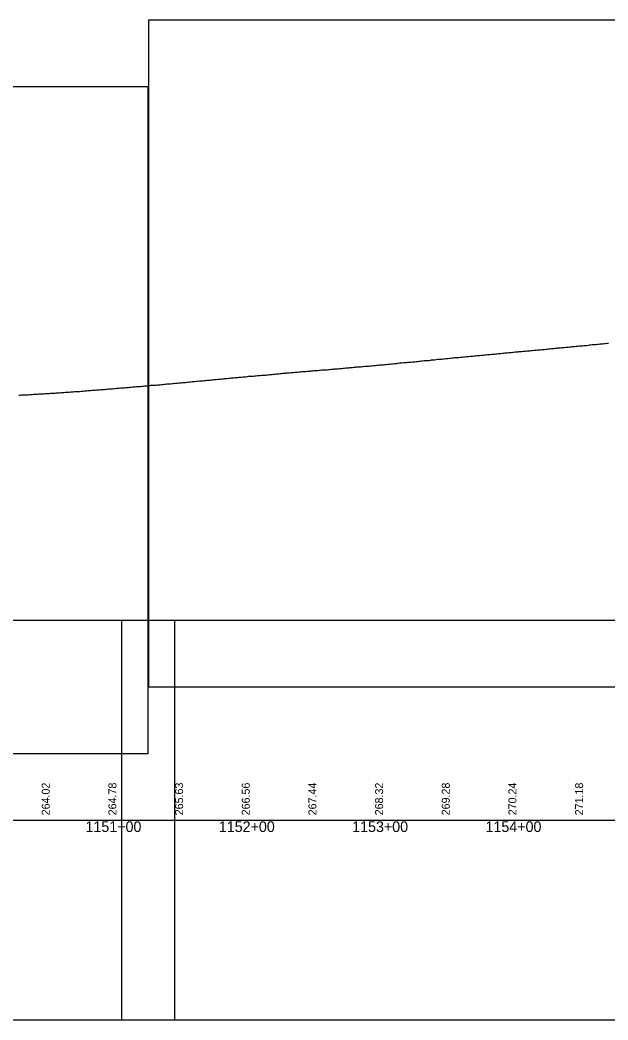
# Model space of a CAD drawing. Extents: x 2898 to 49495, y -15038 to -13538.
# Drawn here: x 4380 to 4821, y -15038 to -14288 of the extents above; entities that cross this region are included whole.
import ezdxf

# ---------------------------------------------------------------- set-up
doc = ezdxf.new("R2010")
doc.units = 0
for name, color, linetype in [('RD_DDB_Profile_EX', 7, 'Continuous'), ('RD_DDB_StaTX', 7, 'Continuous'), ('RD_DDB_StripGrade', 7, 'Continuous'), ('RD_GPK_Profile_Cell', 7, 'Continuous'), ('RD_SHT_ShtClip', 7, 'Continuous')]:
    doc.layers.add(name, color=color, linetype=linetype)

msp = doc.modelspace()

# ---------------------------------------------------------------- linework, layer by layer
at = {"layer": 'RD_DDB_Profile_EX'}
for points in [[(4721.05, -14540.3), (4721.62, -14540.27), (4722.62, -14540.17), (4723.62, -14540.11), (4724.67, -14540.01), (4725.62, -14539.95), (4726.62, -14539.85), (4727.62, -14539.8), (4728.62, -14539.65), (4729.62, -14539.55), (4730.62, -14539.45), (4731.91, -14539.31), (4732.62, -14539.24), (4733.62, -14539.14), (4734.62, -14539.04), (4735.62, -14538.99), (4736.62, -14538.94), (4737.62, -14538.89), (4738.62, -14538.69), (4739.16, -14538.67), (4739.62, -14538.64), (4740.62, -14538.49), (4741.62, -14538.34), (4742.78, -14538.28), (4743.62, -14538.19), (4744.62, -14538.09), (4745.61, -14537.99), (4746.62, -14537.94), (4747.62, -14537.79), (4748.61, -14537.75), (4749.62, -14537.64), (4750.02, -14537.64), (4750.39, -14537.64), (4751.4, -14537.39), (4752.39, -14537.34), (4753.64, -14537.25), (4754.39, -14537.18), (4755.39, -14537.12), (4756.39, -14537.07), (4757.4, -14536.92), (4758.39, -14536.86), (4759.4, -14536.76), (4760.4, -14536.6), (4760.89, -14536.6), (4761.39, -14536.6), (4762.39, -14536.5), (4763.4, -14536.35), (4764.51, -14536.24), (4765.4, -14536.2), (4766.4, -14536.19), (4767.39, -14536.04), (4768.39, -14535.94), (4769.4, -14535.88), (4770.39, -14535.74), (4771.39, -14535.68), (4771.75, -14535.63), (4772.39, -14535.53), (4773.39, -14535.49), (4774.39, -14535.39), (4775.39, -14535.29), (4776.39, -14535.14), (4777.39, -14535.09), (4778.39, -14534.94), (4779, -14534.85), (4779.39, -14534.79), (4780.39, -14534.74), (4781.39, -14534.69), (4782.62, -14534.52), (4783.39, -14534.44), (4784.39, -14534.35), (4785.38, -14534.3), (4786.39, -14534.16), (4787.39, -14534.11), (4788.39, -14533.97), (4789.39, -14533.91), (4790.1, -14533.76), (4791.11, -14533.76), (4792.11, -14533.66), (4793.11, -14533.6), (4793.49, -14533.55), (4794.11, -14533.46), (4795.11, -14533.35), (4796.1, -14533.3), (4797.11, -14533.15), (4798.11, -14533.05), (4799.11, -14532.95), (4800.1, -14532.9), (4800.73, -14532.84), (4801.1, -14532.8), (4802.11, -14532.75), (4803.11, -14532.6), (4804.35, -14532.54), (4805.1, -14532.5), (4806.1, -14532.26), (4807.1, -14532.16), (4808.1, -14532.06), (4809.1, -14531.96), (4810.1, -14531.92), (4811.1, -14531.86), (4811.6, -14531.79), (4812.1, -14531.72)], [(4812.1, -14531.72), (4813.1, -14531.62), (4814.09, -14531.52), (4815.22, -14531.42), (4816.09, -14531.38), (4817.09, -14531.37), (4818.09, -14531.14), (4819.09, -14530.99), (4820.37, -14530.94), (4821.37, -14530.84)], [(4632.3, -14548.69), (4632.77, -14548.66), (4633.76, -14548.61), (4634.12, -14548.59), (4634.77, -14548.56), (4635.76, -14548.5), (4636.76, -14548.45), (4637.77, -14548.3), (4638.77, -14548.15), (4639.76, -14548.04), (4640.77, -14547.99), (4641.36, -14548.02), (4641.76, -14548.04), (4642.77, -14547.84), (4643.76, -14547.73), (4644.99, -14547.67), (4645.77, -14547.63), (4646.77, -14547.48), (4647.76, -14547.38), (4648.76, -14547.23), (4649.77, -14547.18), (4650.77, -14547.13), (4651.76, -14547.03), (4652.23, -14547), (4652.76, -14546.98), (4653.76, -14546.83), (4654.77, -14546.73), (4655.85, -14546.62), (4656.76, -14546.58), (4657.77, -14546.48), (4658.76, -14546.33), (4659.76, -14546.28), (4660.77, -14546.18), (4661.76, -14546.09), (4662.76, -14545.98), (4663.09, -14545.94), (4663.76, -14545.84), (4664.76, -14545.69), (4665.76, -14545.64), (4666.75, -14545.54), (4667.76, -14545.45), (4668.76, -14545.35), (4669.76, -14545.31), (4670.34, -14545.25), (4670.76, -14545.21), (4671.76, -14545.06), (4672.1, -14545.01), (4673.09, -14545), (4674.1, -14544.95), (4675.1, -14544.84), (4676.1, -14544.74), (4677.1, -14544.58), (4677.58, -14544.53), (4678.1, -14544.48), (4679.1, -14544.42), (4680.1, -14544.32), (4681.2, -14544.2), (4682.1, -14544.11), (4683.1, -14543.96), (4684.1, -14543.9), (4685.11, -14543.8), (4686.1, -14543.84), (4687.1, -14543.79), (4688.11, -14543.49), (4688.45, -14543.46), (4689.1, -14543.39), (4690.11, -14543.33), (4691.1, -14543.23), (4692.1, -14543.08), (4693.11, -14542.93), (4694.11, -14542.92), (4695.11, -14542.82), (4695.69, -14542.76), (4696.1, -14542.72), (4697.1, -14542.67), (4698.11, -14542.52), (4699.31, -14542.44), (4700.1, -14542.32), (4701.11, -14542.22), (4702.1, -14542.17), (4703.11, -14542.12), (4704.11, -14541.87), (4705.1, -14541.77), (4706.11, -14541.67), (4706.56, -14541.63), (4707.1, -14541.57), (4708.11, -14541.47), (4709.1, -14541.47), (4710.18, -14541.33), (4710.63, -14541.32), (4711.62, -14541.22), (4712.62, -14541.21), (4713.8, -14541.12), (4714.62, -14540.95), (4715.62, -14540.85), (4716.62, -14540.74), (4717.63, -14540.68), (4718.62, -14540.53), (4719.62, -14540.48), (4720.62, -14540.33), (4721.05, -14540.3)], [(4540.37, -14556.74), (4541.37, -14556.65), (4542.37, -14556.65), (4543.57, -14556.55), (4544.37, -14556.4), (4545.37, -14556.3), (4546.37, -14556.25), (4547.37, -14556.15), (4548.37, -14556.1), (4549.37, -14556), (4550.37, -14555.9), (4550.81, -14555.81), (4551.36, -14555.7), (4552.37, -14555.66), (4553.2, -14555.65), (4554.44, -14555.62), (4555.2, -14555.55), (4556.2, -14555.45), (4557.2, -14555.34), (4558.2, -14555.19), (4559.2, -14555.19), (4560.2, -14555.13), (4561.2, -14554.93), (4561.68, -14554.91), (4562.21, -14554.88), (4563.21, -14554.78), (4564.2, -14554.72), (4565.3, -14554.61), (4566.2, -14554.52), (4567.2, -14554.37), (4568.2, -14554.27), (4569.2, -14554.22), (4570.2, -14554.17), (4571.2, -14554.02), (4572.2, -14553.96), (4572.55, -14553.91), (4573.2, -14553.82), (4574.2, -14553.77), (4575.19, -14553.66), (4576.19, -14553.56), (4577.2, -14553.46), (4578.2, -14553.42), (4579.2, -14553.27), (4579.79, -14553.24), (4580.2, -14553.21), (4581.2, -14553.12), (4582.2, -14553.07), (4583.41, -14552.9), (4584.2, -14552.82), (4585.2, -14552.77), (4586.19, -14552.67), (4587.19, -14552.62), (4588.19, -14552.47), (4589.49, -14552.37), (4590.66, -14552.25), (4591.49, -14552.17), (4592.48, -14552.07), (4593.49, -14552.06), (4594.48, -14552.01), (4595.48, -14551.91), (4596.48, -14551.86), (4597.48, -14551.76), (4597.9, -14551.72), (4598.48, -14551.66), (4599.48, -14551.51), (4600.48, -14551.46), (4601.52, -14551.36), (4602.48, -14551.31), (4603.48, -14551.25), (4604.48, -14551.16), (4605.14, -14551.09), (4605.49, -14551.06), (4606.48, -14550.96), (4607.48, -14550.86), (4608.77, -14550.79), (4609.48, -14550.76), (4610.48, -14550.75), (4611.47, -14550.61), (4612.48, -14550.51), (4613.48, -14550.41), (4614.48, -14550.36), (4615.48, -14550.22), (4616.01, -14550.16), (4616.48, -14550.12), (4617.48, -14550.07), (4618.48, -14549.97), (4619.63, -14549.91), (4620.48, -14549.83), (4621.47, -14549.73), (4622.48, -14549.63), (4623.48, -14549.58), (4624.47, -14549.44), (4625.48, -14549.34), (4626.47, -14549.35), (4626.88, -14549.29), (4627.47, -14549.2), (4628.47, -14549.11), (4629.48, -14549.01), (4630.5, -14548.91), (4631.76, -14548.72), (4632.3, -14548.69)], [(4445.46, -14565.28), (4446.46, -14565.13), (4447.45, -14565.08), (4448.45, -14565.03), (4449.46, -14564.97), (4450.45, -14564.93), (4451.46, -14564.82), (4452.46, -14564.63), (4453.46, -14564.58), (4454.46, -14564.53), (4455.46, -14564.43), (4456.46, -14564.38), (4457.46, -14564.28), (4458.45, -14564.23), (4459.46, -14564.13), (4460.46, -14564.03), (4461.46, -14563.98), (4462.46, -14563.93), (4463.46, -14563.78), (4464.46, -14563.68), (4465.46, -14563.58), (4466.45, -14563.48), (4467.45, -14563.38), (4468.46, -14563.33), (4469.46, -14563.28), (4470.46, -14563.23), (4471.45, -14563.08), (4472.46, -14562.98), (4473.45, -14562.88), (4474.42, -14562.84), (4475.14, -14562.83), (4476.15, -14562.68), (4477.15, -14562.53), (4478.14, -14562.43), (4479.15, -14562.42), (4480.15, -14562.42), (4481.14, -14562.27), (4482.15, -14562.22), (4483.14, -14562.12), (4484.15, -14562.02), (4485.15, -14562.01), (4486.14, -14561.81), (4487.14, -14561.76), (4488.14, -14561.66), (4489.15, -14561.56), (4490.14, -14561.41), (4491.13, -14561.41), (4492.14, -14561.3), (4493.14, -14561.25), (4494.13, -14561.15), (4495.14, -14561), (4496.13, -14560.89), (4496.48, -14560.88), (4497.14, -14560.84), (4498.14, -14560.74), (4499.13, -14560.64), (4500.14, -14560.59), (4501.14, -14560.49), (4502.14, -14560.34), (4503.13, -14560.29), (4503.73, -14560.31), (4504.13, -14560.33), (4505.14, -14560.08), (4506.13, -14559.98), (4507.35, -14559.82), (4508.13, -14559.78), (4509.13, -14559.68), (4510.14, -14559.58), (4511.13, -14559.48), (4512.13, -14559.38), (4513.13, -14559.28), (4514.59, -14559.17), (4515.37, -14559.13), (4516.37, -14559.03), (4517.37, -14558.97), (4518.36, -14558.87), (4519.37, -14558.77), (4520.41, -14558.71), (4521.37, -14558.61), (4521.84, -14558.57), (4522.37, -14558.51), (4523.37, -14558.41), (4524.37, -14558.31), (4525.46, -14558.14), (4526.37, -14558.01), (4527.37, -14558), (4528.37, -14557.95), (4529.37, -14557.85), (4530.37, -14557.8), (4531.37, -14557.65), (4532.37, -14557.5), (4532.7, -14557.48), (4533.37, -14557.45), (4534.37, -14557.35), (4535.37, -14557.25), (4536.37, -14557.15), (4537.36, -14557.09), (4538.37, -14556.95), (4539.37, -14556.84), (4539.95, -14556.79), (4540.37, -14556.74)], [(4379.21, -14569.75), (4380.21, -14569.74), (4381.21, -14569.7), (4382.2, -14569.65), (4383.21, -14569.65), (4384.21, -14569.6), (4385.21, -14569.54), (4386.21, -14569.49), (4387.21, -14569.4), (4388.21, -14569.35), (4389.21, -14569.25), (4390.21, -14569.2), (4391.21, -14569.15), (4392.21, -14569.1), (4393.21, -14569.05), (4394.21, -14568.95), (4394.88, -14568.95), (4395.88, -14568.85), (4396.89, -14568.9), (4397.89, -14568.8), (4398.88, -14568.6), (4399.88, -14568.6), (4400.89, -14568.65), (4401.89, -14568.5), (4402.88, -14568.4), (4403.89, -14568.35), (4404.88, -14568.3), (4405.89, -14568.26), (4406.89, -14568.2), (4407.89, -14568.11), (4408.88, -14568.06), (4409.89, -14568.01), (4410.89, -14567.91), (4411.89, -14567.91), (4412.89, -14567.81), (4413.89, -14567.71), (4414.89, -14567.71), (4415.89, -14567.56), (4416.89, -14567.51), (4417.89, -14567.46), (4418.88, -14567.41), (4419.89, -14567.36), (4420.89, -14567.21), (4421.89, -14567.16), (4422.87, -14567.12), (4423.87, -14567.12), (4424.88, -14567.02), (4425.87, -14566.92), (4426.87, -14566.77), (4427.87, -14566.67), (4428.88, -14566.57), (4429.87, -14566.52), (4430.87, -14566.42), (4431.87, -14566.37), (4432.87, -14566.27), (4433.87, -14566.18), (4434.45, -14566.12), (4435.45, -14566.07), (4436.46, -14565.97), (4437.46, -14565.87), (4438.46, -14565.87), (4439.46, -14565.72), (4440.45, -14565.67), (4441.46, -14565.62), (4442.45, -14565.52), (4443.45, -14565.47), (4444.46, -14565.37), (4445.46, -14565.28)]]:
    msp.add_lwpolyline(points, dxfattribs=at)
at = {"layer": 'RD_GPK_Profile_Cell'}
msp.add_line((2976.05, -14888.47), (48721.13, -14888.47), dxfattribs=at)
at = {"layer": 'RD_SHT_ShtClip'}
for points in [[(5976.22, -14788.47), (5976.22, -14288.47), (5976.22, -14288.47), (4476.38, -14288.47), (4476.38, -14788.47)], [(4476.22, -14838.47), (4476.22, -14338.47), (4476.22, -14338.47), (2976.38, -14338.47), (2976.38, -14838.47)], [(2956.38, -14738.47), (4496.05, -14738.47), (4496.05, -15038.47), (2956.38, -15038.47)], [(4456.38, -14738.47), (5996.05, -14738.47), (5996.05, -15038.47), (4456.38, -15038.47)]]:
    msp.add_lwpolyline(points, close=True, dxfattribs=at)

# ---------------------------------------------------------------- texts
at = {"layer": 'RD_DDB_StaTX'}
for s, p in [('1151+00', (4429.18, -14897.47)), ('1152+00', (4529.18, -14897.47)), ('1153+00', (4629.18, -14897.47)), ('1154+00', (4729.18, -14897.47))]:
    msp.add_text(s, height=8, dxfattribs=at).set_placement(p)
at = {"layer": 'RD_DDB_StripGrade'}
for s, p in [('264.02', (4402.38, -14884.98)), ('264.78', (4452.38, -14884.98)), ('265.63', (4502.38, -14884.98)), ('266.56', (4552.38, -14884.98)), ('267.44', (4602.38, -14884.98)), ('268.32', (4652.38, -14884.98)), ('269.28', (4702.38, -14884.98)), ('270.24', (4752.38, -14884.98)), ('271.18', (4802.38, -14884.98))]:
    msp.add_text(s, height=6, rotation=90, dxfattribs=at).set_placement(p)

doc.saveas('drawing.dxf')
